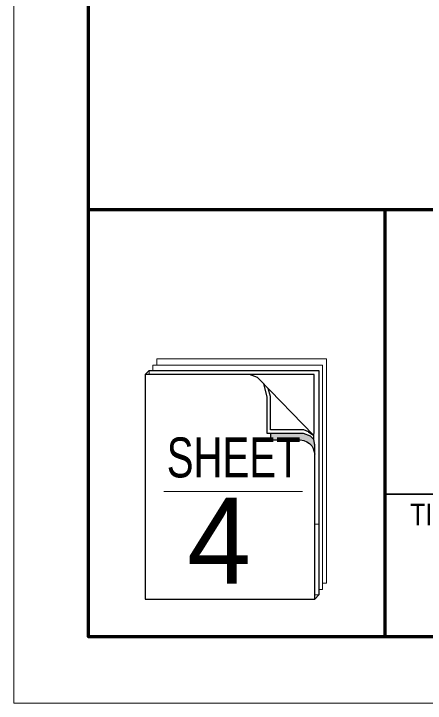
# Model space of a CAD drawing. Extents: x 44.6 to 61.6, y -38.7 to -27.7.
# Drawn here: x 44.56 to 46.005, y -38.699 to -36.276 of the extents above; entities that cross this region are included whole.
import ezdxf
from ezdxf.enums import TextEntityAlignment as Align

# ---------------------------------------------------------------- set-up
doc = ezdxf.new("R2010")
doc.units = 0
doc.header["$LTSCALE"] = 0.025
doc.layers.add('60', color=7, linetype='Continuous', lineweight=13)
doc.layers.add('62', color=7, linetype='Continuous')

msp = doc.modelspace()

# ---------------------------------------------------------------- hatches: boundary and pattern name
at = {"layer": '60'}
msp.add_hatch(color=256, dxfattribs=at).paths.add_polyline_path([(45.4622, -37.75111), (45.4622, -37.77369), (45.56627, -37.77369), (45.57858, -37.77562), (45.58877, -37.77976), (45.59855, -37.78659), (45.60661, -37.79456), (45.61103, -37.80321), (45.61762, -37.82356), (45.6174, -37.79049), (45.61399, -37.77199), (45.60235, -37.75991), (45.577, -37.75059)])

# ---------------------------------------------------------------- linework, layer by layer
at = {"layer": '60', "lineweight": 70}
for p, q in [((48.84124, -36.96462), (44.82119, -36.96462)), ((45.86407, -38.46427), (45.86407, -36.96462))]:
    msp.add_line(p, q, dxfattribs=at)
at = {"layer": '60', "lineweight": 35}
for p, q in [((45.42133, -37.55995), (45.61274, -37.75709)), ((48.84124, -37.96435), (45.86407, -37.96435))]:
    msp.add_line(p, q, dxfattribs=at)
at = {"layer": '60', "lineweight": 25}
msp.add_line((45.59565, -37.7445), (45.61439, -37.75838), dxfattribs=at)
at = {"layer": '60'}
for p, q in [((45.08697, -37.95443), (45.57423, -37.95443)), ((45.63325, -38.06908), (45.61964, -38.06908))]:
    msp.add_line(p, q, dxfattribs=at)
msp.add_lwpolyline([(61.57033, -38.69864), (44.55984, -38.69864), (44.55984, -27.69184), (61.57033, -27.69184)], close=True, dxfattribs=at)
at = {"layer": '60', "lineweight": 70}
msp.add_lwpolyline([(60.8892, -27.90872), (44.82119, -27.90872), (44.82119, -38.46427), (60.8892, -38.46427)], close=True, dxfattribs=at)
at = {"layer": '60'}
for points in [[(45.06231, -37.51055), (45.06231, -37.48822), (45.65817, -37.48822), (45.65817, -38.27722), (45.64467, -38.27722)], [(45.04875, -37.52916), (45.04875, -37.51055), (45.64467, -37.51055), (45.64467, -38.29957), (45.63112, -38.29957)], [(45.03521, -37.54404), (45.03521, -37.52916), (45.63112, -37.52916), (45.63112, -38.3182), (45.61762, -38.3182)]]:
    msp.add_lwpolyline(points, dxfattribs=at)
at = {"layer": '60', "lineweight": 25}
for points in [[(45.61531, -37.54383), (45.43415, -37.54383), (45.38734, -37.54404), (45.02164, -37.54404), (45.03521, -37.52916), (45.63112, -37.52916), (45.63112, -38.3182), (45.61762, -38.33306), (45.61762, -37.84741), (45.61762, -37.79162), (45.61399, -37.77199), (45.61531, -37.73053)], [(45.02164, -38.33306), (45.61762, -38.33306), (45.61762, -37.84741), (45.61762, -37.81664), (45.61762, -37.79162), (45.61762, -37.79162), (45.61399, -37.77199), (45.60235, -37.75991), (45.577, -37.75059), (45.44998, -37.75059), (45.44998, -37.62223), (45.43765, -37.57673), (45.41578, -37.5543), (45.38734, -37.54404), (45.02164, -37.54404)], [(45.4622, -37.75111), (45.4622, -37.77369), (45.56627, -37.77369), (45.57858, -37.77562), (45.58877, -37.77976), (45.59855, -37.78659), (45.60661, -37.79456), (45.61103, -37.80321), (45.61762, -37.82356), (45.6174, -37.79049), (45.61399, -37.77199), (45.60235, -37.75991), (45.577, -37.75059)]]:
    msp.add_lwpolyline(points, close=True, dxfattribs=at)
msp.add_lwpolyline([(45.59565, -37.7445), (45.57915, -37.73845), (45.46218, -37.73845), (45.46218, -37.62031), (45.45362, -37.59321)], dxfattribs=at)

# ---------------------------------------------------------------- texts
at = {"layer": '60'}
for s, height, width, p in [('SHEET', 0.1405, 0.75, (45.33212, -37.90527)), ('TITLE:', 0.07704, 0.85, (46.08368, -38.07395))]:
    msp.add_text(s, height=height, dxfattribs=dict(at, width=width)).set_placement(p, align=Align.CENTER)
at = {"layer": '62'}
msp.add_text('4 ', height=0.3024, dxfattribs=at).set_placement((45.33749, -38.2783), align=Align.CENTER)

doc.saveas('drawing.dxf')
